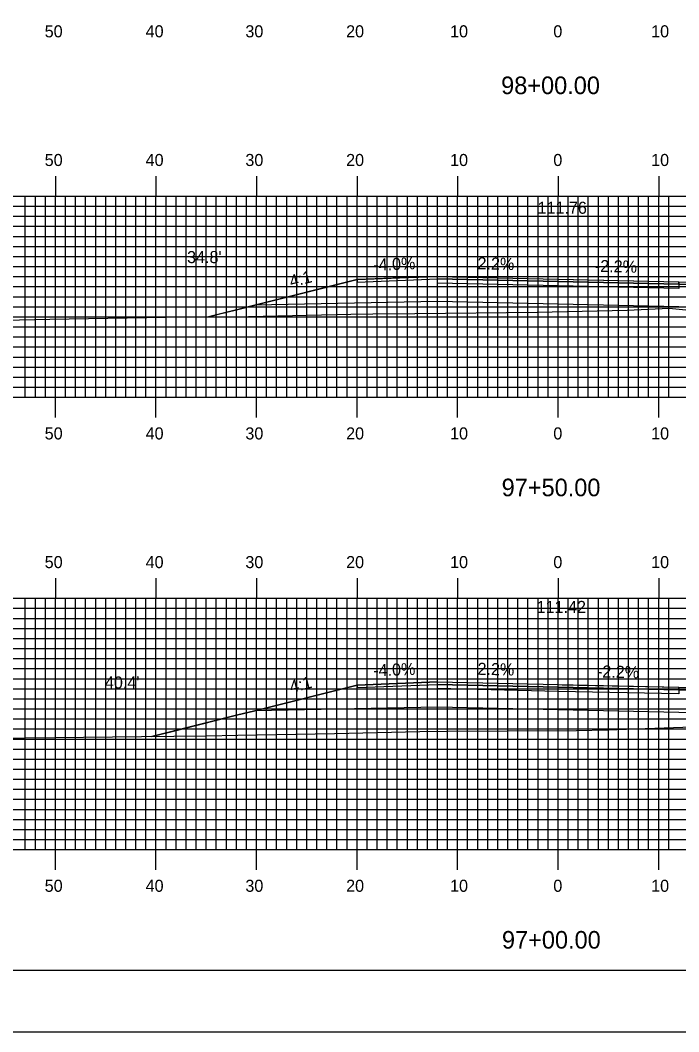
# Model space of a CAD drawing. Extents: x 1766120 to 1766463, y 442591 to 442811.
# Drawn here: x 1766231.9 to 1766297.4, y 442590.5 to 442691.2 of the extents above; entities that cross this region are included whole.
import ezdxf

# ---------------------------------------------------------------- set-up
doc = ezdxf.new("R2010")
doc.units = 0
for name, color, linetype in [('ANNOTATION', 7, 'Continuous'), ('BORDER', 7, 'Continuous'), ('D_Roadway_Centerline', 7, 'Continuous'), ('D_Roadway_Centerline_Text', 7, 'Continuous'), ('D_Roadway_Edge_Shoulder', 7, 'Continuous'), ('D_Roadway_Edge_TW', 7, 'Continuous'), ('D_Roadway_Pavement', 7, 'Continuous'), ('D_Roadway_SlopeLines', 7, 'Continuous'), ('D_Roadway_SubGrade', 7, 'Continuous'), ('D_Text_Standard', 7, 'Continuous'), ('H_V ANNOTATION', 7, 'Continuous'), ('MAJOR', 7, 'Continuous'), ('MINOR', 7, 'Continuous'), ('PLOT BOUNDARY', 7, 'Continuous'), ('S_Roadway_Centerline', 7, 'Continuous')]:
    doc.layers.add(name, color=color, linetype=linetype)

msp = doc.modelspace()

# ---------------------------------------------------------------- linework, layer by layer
at = {"layer": 'BORDER'}
msp.add_lwpolyline([(1766135.8, 442596.67), (1766455.8, 442596.67), (1766455.8, 442806.67), (1766135.8, 442806.67)], close=True, dxfattribs=at)
at = {"layer": 'D_Roadway_Centerline'}
for points in [[(1766250.63, 442661.68), (1766251.62, 442661.92), (1766253.4, 442662.37), (1766255.22, 442662.83), (1766262.93, 442664.75), (1766265.39, 442665.37), (1766265.4, 442665.37), (1766269.63, 442665.54), (1766273.4, 442665.69), (1766285.4, 442665.42), (1766285.4, 442665.42), (1766289.96, 442665.32), (1766297.39, 442665.16), (1766297.4, 442665.16), (1766305.4, 442664.84)], [(1766244.99, 442619.92), (1766247.79, 442620.62), (1766253.4, 442622.03), (1766253.4, 442622.03), (1766255.22, 442622.48), (1766255.23, 442622.48), (1766261.12, 442623.95), (1766265.4, 442625.03), (1766265.4, 442625.03), (1766273.4, 442625.35), (1766273.4, 442625.35), (1766285.4, 442625.08), (1766285.8, 442625.07), (1766297.39, 442624.82), (1766297.4, 442624.82), (1766305.4, 442624.5), (1766305.4, 442624.5), (1766305.4, 442624.5), (1766315.57, 442621.95), (1766319.93, 442620.86)]]:
    msp.add_lwpolyline(points, dxfattribs=at)
at = {"layer": 'D_Roadway_Edge_Shoulder'}
for points in [[(1766273.4, 442665.69), (1766265.4, 442665.37), (1766265.4, 442665.12), (1766273.4, 442665.44)], [(1766297.4, 442665.16), (1766305.4, 442664.84), (1766305.4, 442664.59), (1766297.4, 442664.91)], [(1766273.4, 442625.35), (1766265.4, 442625.03), (1766265.4, 442624.78), (1766273.4, 442625.1)], [(1766297.4, 442624.82), (1766305.4, 442624.5), (1766305.4, 442624.25), (1766297.4, 442624.57)]]:
    msp.add_lwpolyline(points, close=True, dxfattribs=at)
at = {"layer": 'D_Roadway_Edge_TW'}
for points in [[(1766273.4, 442665.44), (1766273.4, 442665.69), (1766285.4, 442665.42), (1766297.4, 442665.16), (1766297.4, 442664.91), (1766285.4, 442665.17)], [(1766273.4, 442625.1), (1766273.4, 442625.35), (1766285.4, 442625.08), (1766297.4, 442624.82), (1766297.4, 442624.57), (1766285.4, 442624.83)]]:
    msp.add_lwpolyline(points, close=True, dxfattribs=at)
at = {"layer": 'D_Roadway_Pavement'}
for points in [[(1766273.4, 442665.02), (1766273.4, 442665.44), (1766285.4, 442665.17), (1766297.4, 442664.91), (1766297.4, 442664.49), (1766285.4, 442664.76)], [(1766273.4, 442624.68), (1766273.4, 442625.1), (1766285.4, 442624.83), (1766297.4, 442624.57), (1766297.4, 442624.15), (1766285.4, 442624.41)]]:
    msp.add_lwpolyline(points, close=True, dxfattribs=at)
at = {"layer": 'D_Roadway_SlopeLines'}
for points in [[(1766265.4, 442665.37), (1766255.22, 442662.83), (1766253.4, 442662.37), (1766250.63, 442661.68)], [(1766265.4, 442625.03), (1766255.22, 442622.48), (1766253.4, 442622.03), (1766244.99, 442619.92)]]:
    msp.add_lwpolyline(points, dxfattribs=at)
at = {"layer": 'D_Roadway_SubGrade'}
for points in [[(1766273.4, 442663.19), (1766255.22, 442662.83), (1766265.4, 442665.37), (1766265.4, 442665.12), (1766273.4, 442665.44), (1766285.4, 442665.17), (1766297.4, 442664.91), (1766305.4, 442664.59), (1766305.4, 442664.84), (1766315.57, 442662.3), (1766297.4, 442662.66), (1766285.4, 442662.92)], [(1766273.4, 442622.85), (1766255.22, 442622.48), (1766265.4, 442625.03), (1766265.4, 442624.78), (1766273.4, 442625.1), (1766285.4, 442624.83), (1766297.4, 442624.57), (1766305.4, 442624.25), (1766305.4, 442624.5), (1766315.57, 442621.95), (1766297.4, 442622.32), (1766285.4, 442622.58)]]:
    msp.add_lwpolyline(points, close=True, dxfattribs=at)
at = {"layer": 'MAJOR'}
for p, q in [((1766235.4, 442675.67), (1766235.4, 442673.67)), ((1766245.4, 442675.67), (1766245.4, 442673.67)), ((1766255.4, 442675.67), (1766255.4, 442673.67)), ((1766265.4, 442675.67), (1766265.4, 442673.67)), ((1766275.4, 442675.67), (1766275.4, 442673.67)), ((1766285.4, 442675.67), (1766285.4, 442673.67)), ((1766295.4, 442675.67), (1766295.4, 442673.67)), ((1766145.4, 442673.67), (1766425.4, 442673.67)), ((1766145.4, 442673.67), (1766425.4, 442673.67)), ((1766235.4, 442653.67), (1766235.4, 442673.67)), ((1766245.4, 442653.67), (1766245.4, 442673.67)), ((1766255.4, 442653.67), (1766255.4, 442673.67)), ((1766265.4, 442653.67), (1766265.4, 442673.67)), ((1766275.4, 442653.67), (1766275.4, 442673.67)), ((1766285.4, 442653.67), (1766285.4, 442673.67)), ((1766295.4, 442653.67), (1766295.4, 442673.67)), ((1766145.4, 442668.67), (1766425.4, 442668.67)), ((1766145.4, 442663.67), (1766425.4, 442663.67)), ((1766145.4, 442658.67), (1766425.4, 442658.67)), ((1766145.4, 442653.67), (1766425.4, 442653.67)), ((1766145.4, 442653.67), (1766425.4, 442653.67)), ((1766235.4, 442651.66), (1766235.4, 442653.67)), ((1766245.4, 442651.66), (1766245.4, 442653.67)), ((1766255.4, 442651.66), (1766255.4, 442653.67)), ((1766265.4, 442651.66), (1766265.4, 442653.67)), ((1766275.4, 442651.66), (1766275.4, 442653.67)), ((1766285.4, 442651.66), (1766285.4, 442653.67)), ((1766295.4, 442651.66), (1766295.4, 442653.67)), ((1766235.4, 442635.67), (1766235.4, 442633.67)), ((1766245.4, 442635.67), (1766245.4, 442633.67)), ((1766255.4, 442635.67), (1766255.4, 442633.67)), ((1766265.4, 442635.67), (1766265.4, 442633.67)), ((1766275.4, 442635.67), (1766275.4, 442633.67)), ((1766285.4, 442635.67), (1766285.4, 442633.67)), ((1766295.4, 442635.67), (1766295.4, 442633.67)), ((1766145.4, 442633.67), (1766425.4, 442633.67)), ((1766145.4, 442633.67), (1766425.4, 442633.67)), ((1766235.4, 442608.67), (1766235.4, 442633.67)), ((1766245.4, 442608.67), (1766245.4, 442633.67)), ((1766255.4, 442608.67), (1766255.4, 442633.67)), ((1766265.4, 442608.67), (1766265.4, 442633.67)), ((1766275.4, 442608.67), (1766275.4, 442633.67)), ((1766285.4, 442608.67), (1766285.4, 442633.67)), ((1766295.4, 442608.67), (1766295.4, 442633.67)), ((1766145.4, 442628.67), (1766425.4, 442628.67)), ((1766145.4, 442623.67), (1766425.4, 442623.67)), ((1766145.4, 442618.67), (1766425.4, 442618.67)), ((1766145.4, 442613.67), (1766425.4, 442613.67)), ((1766145.4, 442608.67), (1766425.4, 442608.67)), ((1766145.4, 442608.67), (1766425.4, 442608.67)), ((1766235.4, 442606.66), (1766235.4, 442608.67)), ((1766245.4, 442606.66), (1766245.4, 442608.67)), ((1766255.4, 442606.66), (1766255.4, 442608.67)), ((1766265.4, 442606.66), (1766265.4, 442608.67)), ((1766275.4, 442606.66), (1766275.4, 442608.67)), ((1766285.4, 442606.66), (1766285.4, 442608.67)), ((1766295.4, 442606.66), (1766295.4, 442608.67))]:
    msp.add_line(p, q, dxfattribs=at)
at = {"layer": 'MINOR'}
for p, q in [((1766232.4, 442653.67), (1766232.4, 442673.67)), ((1766233.4, 442653.67), (1766233.4, 442673.67)), ((1766234.4, 442653.67), (1766234.4, 442673.67)), ((1766236.4, 442653.67), (1766236.4, 442673.67)), ((1766237.4, 442653.67), (1766237.4, 442673.67)), ((1766238.4, 442653.67), (1766238.4, 442673.67)), ((1766239.4, 442653.67), (1766239.4, 442673.67)), ((1766240.4, 442653.67), (1766240.4, 442673.67)), ((1766241.4, 442653.67), (1766241.4, 442673.67)), ((1766242.4, 442653.67), (1766242.4, 442673.67)), ((1766243.4, 442653.67), (1766243.4, 442673.67)), ((1766244.4, 442653.67), (1766244.4, 442673.67)), ((1766246.4, 442653.67), (1766246.4, 442673.67)), ((1766247.4, 442653.67), (1766247.4, 442673.67)), ((1766248.4, 442653.67), (1766248.4, 442673.67)), ((1766249.4, 442653.67), (1766249.4, 442673.67)), ((1766250.4, 442653.67), (1766250.4, 442673.67)), ((1766251.4, 442653.67), (1766251.4, 442673.67)), ((1766252.4, 442653.67), (1766252.4, 442673.67)), ((1766253.4, 442653.67), (1766253.4, 442673.67)), ((1766254.4, 442653.67), (1766254.4, 442673.67)), ((1766256.4, 442653.67), (1766256.4, 442673.67)), ((1766257.4, 442653.67), (1766257.4, 442673.67)), ((1766258.4, 442653.67), (1766258.4, 442673.67)), ((1766259.4, 442653.67), (1766259.4, 442673.67)), ((1766260.4, 442653.67), (1766260.4, 442673.67)), ((1766261.4, 442653.67), (1766261.4, 442673.67)), ((1766262.4, 442653.67), (1766262.4, 442673.67)), ((1766263.4, 442653.67), (1766263.4, 442673.67)), ((1766264.4, 442653.67), (1766264.4, 442673.67)), ((1766266.4, 442653.67), (1766266.4, 442673.67)), ((1766267.4, 442653.67), (1766267.4, 442673.67)), ((1766268.4, 442653.67), (1766268.4, 442673.67)), ((1766269.4, 442653.67), (1766269.4, 442673.67)), ((1766270.4, 442653.67), (1766270.4, 442673.67)), ((1766271.4, 442653.67), (1766271.4, 442673.67)), ((1766272.4, 442653.67), (1766272.4, 442673.67)), ((1766273.4, 442653.67), (1766273.4, 442673.67)), ((1766274.4, 442653.67), (1766274.4, 442673.67)), ((1766276.4, 442653.67), (1766276.4, 442673.67)), ((1766277.4, 442653.67), (1766277.4, 442673.67)), ((1766278.4, 442653.67), (1766278.4, 442673.67)), ((1766279.4, 442653.67), (1766279.4, 442673.67)), ((1766280.4, 442653.67), (1766280.4, 442673.67)), ((1766281.4, 442653.67), (1766281.4, 442673.67)), ((1766282.4, 442653.67), (1766282.4, 442673.67)), ((1766283.4, 442653.67), (1766283.4, 442673.67)), ((1766284.4, 442653.67), (1766284.4, 442673.67)), ((1766286.4, 442653.67), (1766286.4, 442673.67)), ((1766287.4, 442653.67), (1766287.4, 442673.67)), ((1766288.4, 442653.67), (1766288.4, 442673.67)), ((1766289.4, 442653.67), (1766289.4, 442673.67)), ((1766290.4, 442653.67), (1766290.4, 442673.67)), ((1766291.4, 442653.67), (1766291.4, 442673.67)), ((1766292.4, 442653.67), (1766292.4, 442673.67)), ((1766293.4, 442653.67), (1766293.4, 442673.67)), ((1766294.4, 442653.67), (1766294.4, 442673.67)), ((1766296.4, 442653.67), (1766296.4, 442673.67)), ((1766145.4, 442672.67), (1766425.4, 442672.67)), ((1766145.4, 442671.67), (1766425.4, 442671.67)), ((1766145.4, 442670.67), (1766425.4, 442670.67)), ((1766145.4, 442669.67), (1766425.4, 442669.67)), ((1766145.4, 442667.67), (1766425.4, 442667.67)), ((1766145.4, 442666.67), (1766425.4, 442666.67)), ((1766145.4, 442665.67), (1766425.4, 442665.67)), ((1766145.4, 442664.67), (1766425.4, 442664.67)), ((1766145.4, 442662.67), (1766425.4, 442662.67)), ((1766145.4, 442661.67), (1766425.4, 442661.67)), ((1766145.4, 442660.67), (1766425.4, 442660.67)), ((1766145.4, 442659.67), (1766425.4, 442659.67)), ((1766145.4, 442657.67), (1766425.4, 442657.67)), ((1766145.4, 442656.67), (1766425.4, 442656.67)), ((1766145.4, 442655.67), (1766425.4, 442655.67)), ((1766145.4, 442654.67), (1766425.4, 442654.67)), ((1766232.4, 442608.67), (1766232.4, 442633.67)), ((1766233.4, 442608.67), (1766233.4, 442633.67)), ((1766234.4, 442608.67), (1766234.4, 442633.67)), ((1766236.4, 442608.67), (1766236.4, 442633.67)), ((1766237.4, 442608.67), (1766237.4, 442633.67)), ((1766238.4, 442608.67), (1766238.4, 442633.67)), ((1766239.4, 442608.67), (1766239.4, 442633.67)), ((1766240.4, 442608.67), (1766240.4, 442633.67)), ((1766241.4, 442608.67), (1766241.4, 442633.67)), ((1766242.4, 442608.67), (1766242.4, 442633.67)), ((1766243.4, 442608.67), (1766243.4, 442633.67)), ((1766244.4, 442608.67), (1766244.4, 442633.67)), ((1766246.4, 442608.67), (1766246.4, 442633.67)), ((1766247.4, 442608.67), (1766247.4, 442633.67)), ((1766248.4, 442608.67), (1766248.4, 442633.67)), ((1766249.4, 442608.67), (1766249.4, 442633.67)), ((1766250.4, 442608.67), (1766250.4, 442633.67)), ((1766251.4, 442608.67), (1766251.4, 442633.67)), ((1766252.4, 442608.67), (1766252.4, 442633.67)), ((1766253.4, 442608.67), (1766253.4, 442633.67)), ((1766254.4, 442608.67), (1766254.4, 442633.67)), ((1766256.4, 442608.67), (1766256.4, 442633.67)), ((1766257.4, 442608.67), (1766257.4, 442633.67)), ((1766258.4, 442608.67), (1766258.4, 442633.67)), ((1766259.4, 442608.67), (1766259.4, 442633.67)), ((1766260.4, 442608.67), (1766260.4, 442633.67)), ((1766261.4, 442608.67), (1766261.4, 442633.67)), ((1766262.4, 442608.67), (1766262.4, 442633.67)), ((1766263.4, 442608.67), (1766263.4, 442633.67)), ((1766264.4, 442608.67), (1766264.4, 442633.67)), ((1766266.4, 442608.67), (1766266.4, 442633.67)), ((1766267.4, 442608.67), (1766267.4, 442633.67)), ((1766268.4, 442608.67), (1766268.4, 442633.67)), ((1766269.4, 442608.67), (1766269.4, 442633.67)), ((1766270.4, 442608.67), (1766270.4, 442633.67)), ((1766271.4, 442608.67), (1766271.4, 442633.67)), ((1766272.4, 442608.67), (1766272.4, 442633.67)), ((1766273.4, 442608.67), (1766273.4, 442633.67)), ((1766274.4, 442608.67), (1766274.4, 442633.67)), ((1766276.4, 442608.67), (1766276.4, 442633.67)), ((1766277.4, 442608.67), (1766277.4, 442633.67)), ((1766278.4, 442608.67), (1766278.4, 442633.67)), ((1766279.4, 442608.67), (1766279.4, 442633.67)), ((1766280.4, 442608.67), (1766280.4, 442633.67)), ((1766281.4, 442608.67), (1766281.4, 442633.67)), ((1766282.4, 442608.67), (1766282.4, 442633.67)), ((1766283.4, 442608.67), (1766283.4, 442633.67)), ((1766284.4, 442608.67), (1766284.4, 442633.67)), ((1766286.4, 442608.67), (1766286.4, 442633.67)), ((1766287.4, 442608.67), (1766287.4, 442633.67)), ((1766288.4, 442608.67), (1766288.4, 442633.67)), ((1766289.4, 442608.67), (1766289.4, 442633.67)), ((1766290.4, 442608.67), (1766290.4, 442633.67)), ((1766291.4, 442608.67), (1766291.4, 442633.67)), ((1766292.4, 442608.67), (1766292.4, 442633.67)), ((1766293.4, 442608.67), (1766293.4, 442633.67)), ((1766294.4, 442608.67), (1766294.4, 442633.67)), ((1766296.4, 442608.67), (1766296.4, 442633.67)), ((1766145.4, 442632.67), (1766425.4, 442632.67)), ((1766145.4, 442631.67), (1766425.4, 442631.67)), ((1766145.4, 442630.67), (1766425.4, 442630.67)), ((1766145.4, 442629.67), (1766425.4, 442629.67)), ((1766145.4, 442627.67), (1766425.4, 442627.67)), ((1766145.4, 442626.67), (1766425.4, 442626.67)), ((1766145.4, 442625.67), (1766425.4, 442625.67)), ((1766145.4, 442624.67), (1766425.4, 442624.67)), ((1766145.4, 442622.67), (1766425.4, 442622.67)), ((1766145.4, 442621.67), (1766425.4, 442621.67)), ((1766145.4, 442620.67), (1766425.4, 442620.67)), ((1766145.4, 442619.67), (1766425.4, 442619.67)), ((1766145.4, 442617.67), (1766425.4, 442617.67)), ((1766145.4, 442616.67), (1766425.4, 442616.67)), ((1766145.4, 442615.67), (1766425.4, 442615.67)), ((1766145.4, 442614.67), (1766425.4, 442614.67)), ((1766145.4, 442612.67), (1766425.4, 442612.67)), ((1766145.4, 442611.67), (1766425.4, 442611.67)), ((1766145.4, 442610.67), (1766425.4, 442610.67)), ((1766145.4, 442609.67), (1766425.4, 442609.67))]:
    msp.add_line(p, q, dxfattribs=at)
at = {"layer": 'PLOT BOUNDARY'}
msp.add_lwpolyline([(1766119.61, 442590.55), (1766459.61, 442590.55), (1766459.61, 442810.55), (1766119.61, 442810.55)], close=True, dxfattribs=at)
at = {"layer": 'S_Roadway_Centerline'}
for points in [[(1766230.29, 442661.32), (1766234.85, 442661.44), (1766242.52, 442661.58), (1766246.46, 442661.65), (1766254.61, 442661.7), (1766264.78, 442661.92), (1766266.98, 442661.97), (1766271.14, 442662.01), (1766283.31, 442662.12), (1766292.28, 442662.32), (1766296.45, 442662.52), (1766301.09, 442662.08)], [(1766226.53, 442619.72), (1766235.34, 442619.81), (1766238.19, 442619.84), (1766243.96, 442619.91), (1766250.38, 442619.98), (1766253.54, 442620.06), (1766263.16, 442620.23), (1766271.63, 442620.42), (1766274.4, 442620.45), (1766280.36, 442620.47), (1766287.23, 442620.52), (1766290.31, 442620.59), (1766299.69, 442620.9)]]:
    msp.add_lwpolyline(points, dxfattribs=at)

# ---------------------------------------------------------------- texts
at = {"layer": 'ANNOTATION'}
for s, rotation, p in [('-4.0%', 2.2906, (1766267.03, 442666.24)), ('2.2%', 358.7398, (1766277.37, 442666.4)), ('-2.2%', 358.7396, (1766289.04, 442666.14)), ('4:1', 14.034, (1766258.84, 442664.59)), ('-4.0%', 2.2905, (1766267.03, 442625.89)), ('2.2%', 358.7397, (1766277.37, 442626.06)), ('-2.2%', 358.7397, (1766289.25, 442625.8)), ('4:1', 14.0393, (1766258.85, 442624.25))]:
    msp.add_text(s, height=1.2, rotation=rotation, dxfattribs=at).set_placement(p)
at = {"layer": 'D_Roadway_Centerline'}
for s, p in [('C', (1766285.39, 442665.42)), ('L', (1766285.4, 442665.42)), ('C', (1766285.39, 442625.08)), ('L', (1766285.4, 442625.07))]:
    msp.add_text(s, height=0.0146, dxfattribs=at).set_placement(p)
at = {"layer": 'D_Roadway_Centerline_Text'}
for s, p in [('111.76', (1766283.35, 442671.92)), ('111.42', (1766283.26, 442632.21))]:
    msp.add_text(s, height=1.2, dxfattribs=at).set_placement(p)
at = {"layer": 'D_Text_Standard'}
for s, p in [("34.8'", (1766248.49, 442667.01)), ("40.4'", (1766240.32, 442624.69))]:
    msp.add_text(s, height=1.2, dxfattribs=at).set_placement(p)
at = {"layer": 'H_V ANNOTATION'}
for s, height, p in [('50', 1.2, (1766234.33, 442689.47)), ('40', 1.2, (1766244.37, 442689.47)), ('30', 1.2, (1766254.29, 442689.47)), ('20', 1.2, (1766264.31, 442689.47)), ('10', 1.2, (1766274.65, 442689.47)), ('0', 1.2, (1766284.92, 442689.47)), ('10', 1.2, (1766294.65, 442689.47)), ('98+00.00', 1.75, (1766279.73, 442683.82)), ('50', 1.2, (1766234.33, 442676.67)), ('40', 1.2, (1766244.37, 442676.67)), ('30', 1.2, (1766254.29, 442676.67)), ('20', 1.2, (1766264.31, 442676.67)), ('10', 1.2, (1766274.65, 442676.67)), ('0', 1.2, (1766284.92, 442676.67)), ('10', 1.2, (1766294.65, 442676.67)), ('50', 1.2, (1766234.33, 442649.47)), ('40', 1.2, (1766244.37, 442649.47)), ('30', 1.2, (1766254.29, 442649.47)), ('20', 1.2, (1766264.31, 442649.47)), ('10', 1.2, (1766274.65, 442649.47)), ('0', 1.2, (1766284.92, 442649.47)), ('10', 1.2, (1766294.65, 442649.47)), ('97+50.00', 1.75, (1766279.78, 442643.82)), ('50', 1.2, (1766234.33, 442636.67)), ('40', 1.2, (1766244.37, 442636.67)), ('30', 1.2, (1766254.29, 442636.67)), ('20', 1.2, (1766264.31, 442636.67)), ('10', 1.2, (1766274.65, 442636.67)), ('0', 1.2, (1766284.92, 442636.67)), ('10', 1.2, (1766294.65, 442636.67)), ('50', 1.2, (1766234.33, 442604.47)), ('40', 1.2, (1766244.37, 442604.47)), ('30', 1.2, (1766254.29, 442604.47)), ('20', 1.2, (1766264.31, 442604.47)), ('10', 1.2, (1766274.65, 442604.47)), ('0', 1.2, (1766284.92, 442604.47)), ('10', 1.2, (1766294.65, 442604.47)), ('97+00.00', 1.75, (1766279.81, 442598.82))]:
    msp.add_text(s, height=height, dxfattribs=at).set_placement(p)

doc.saveas('drawing.dxf')
